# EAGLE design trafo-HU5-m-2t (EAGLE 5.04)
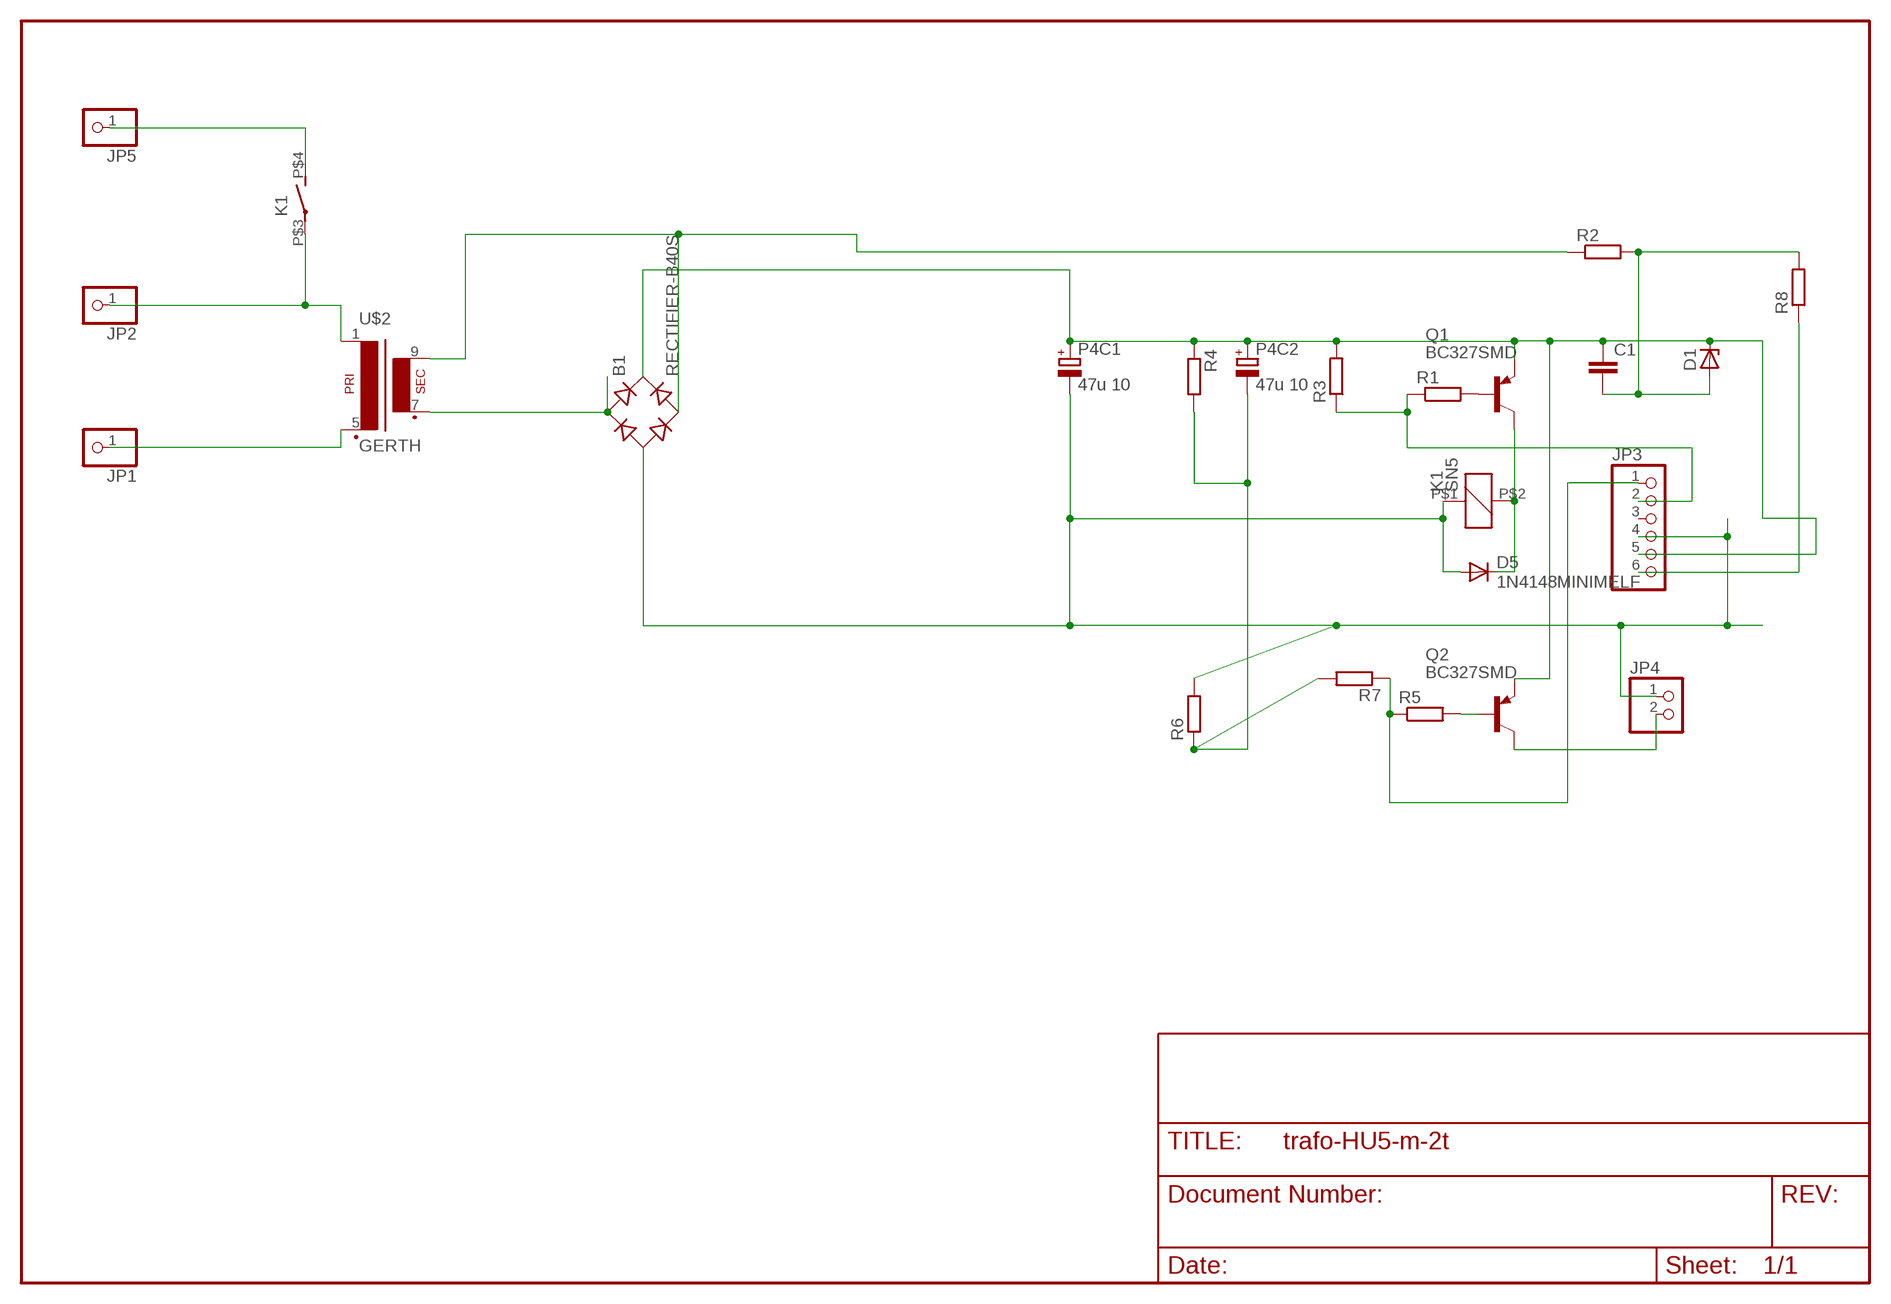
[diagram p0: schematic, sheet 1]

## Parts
B1  RECTIFIER-B40S  [B40S]
C1  C-EUC1206  [C1206]
D1  ZENER-DIODESOT23  [SOT23]
D5  1N4148MINIMELF  [MINIMELF]
JP1  PINHD-1X1  [1X01]
JP2  PINHD-1X1  [1X01]
JP3  PINHD-1X6  [1X06]
JP4  PINHD-1X2  [1X02]
JP5  PINHD-1X1  [1X01]
K1  SN5  [HU]
P4C1  47u 10  CPOL-EUE2-5  [E2-5]
P4C2  47u 10  CPOL-EUSANYO_SMD_A5  [SANYO-OSCON_SMD_A5]
Q1  BC327SMD  [SOT23-BEC]
Q2  BC327SMD  [SOT23-BEC]
R1  R-EU_R0805  [R0805]
R2  R-EU_R0805  [R0805]
R3  R-EU_R1206  [R1206]
R4  R-EU_R0805  [R0805]
R5  R-EU_R0805  [R0805]
R6  R-EU_R0805  [R0805]
R7  R-EU_R0805  [R0805]
R8  R-EU_R1206  [R1206]
U$2  GERTH  [150.06]

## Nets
N$1: JP2.1 K1.P$3(2:P) U$2.1
N$2: B1.+ C1.1 D1.3(C) JP3.5 P4C1.+ P4C2.+ Q1.E Q2.E R3.2 R4.1
N$3: B1.- D5.A JP3.4 JP4.1 K1.P$1 P4C1.- R6.2
N$4: JP5.1 K1.P$4(2:S)
N$5: JP1.1 U$2.5(P2)
N$6: B1.AC1 U$2.7(S3)
N$7: B1.AC2 R2.1 U$2.9(S4)
N$8: Q1.B R1.2
N$9: C1.2 D1.1(A) R2.2 R8.2
N$10: JP3.2 R1.1 R3.1
N$11: D5.C K1.P$2 Q1.C
N$12: JP4.2 Q2.C
N$13: JP3.1 R5.1 R7.1
N$14: JP3.6 R8.1
N$15: Q2.B R5.2
N$16: P4C2.- R4.2 R6.1 R7.2
Unconnected: JP3.3

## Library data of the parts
B1 = rectifier:RECTIFIER-: Rectifier
C1 = rcl-2:C-EU: CAPACITOR, European symbol
D1 = diode-1:ZENER-DIODE: Z-Diode
D5 = diode-1:1N4148: DIODE
JP1 JP2 JP5 = pinhead(2):PINHD-1X1: PIN HEADER
JP3 = pinhead:PINHD-1X6: PIN HEADER
JP4 = pinhead:PINHD-1X2: PIN HEADER
K1 = relay:SN*: Slim PCB Relay 1 pole 6 A SCHRACK Source: http://www.schrack.com/.. 5815.pdf
P4C1 P4C2 = rcl:CPOL-EU: POLARIZED CAPACITOR, European symbol
Q1 Q2 = transistor-pnp:BC327*: PNP Transistror
R1-R8 = rcl-2:R-EU_: RESISTOR, European symbol
U$2 = trafo:GERTH

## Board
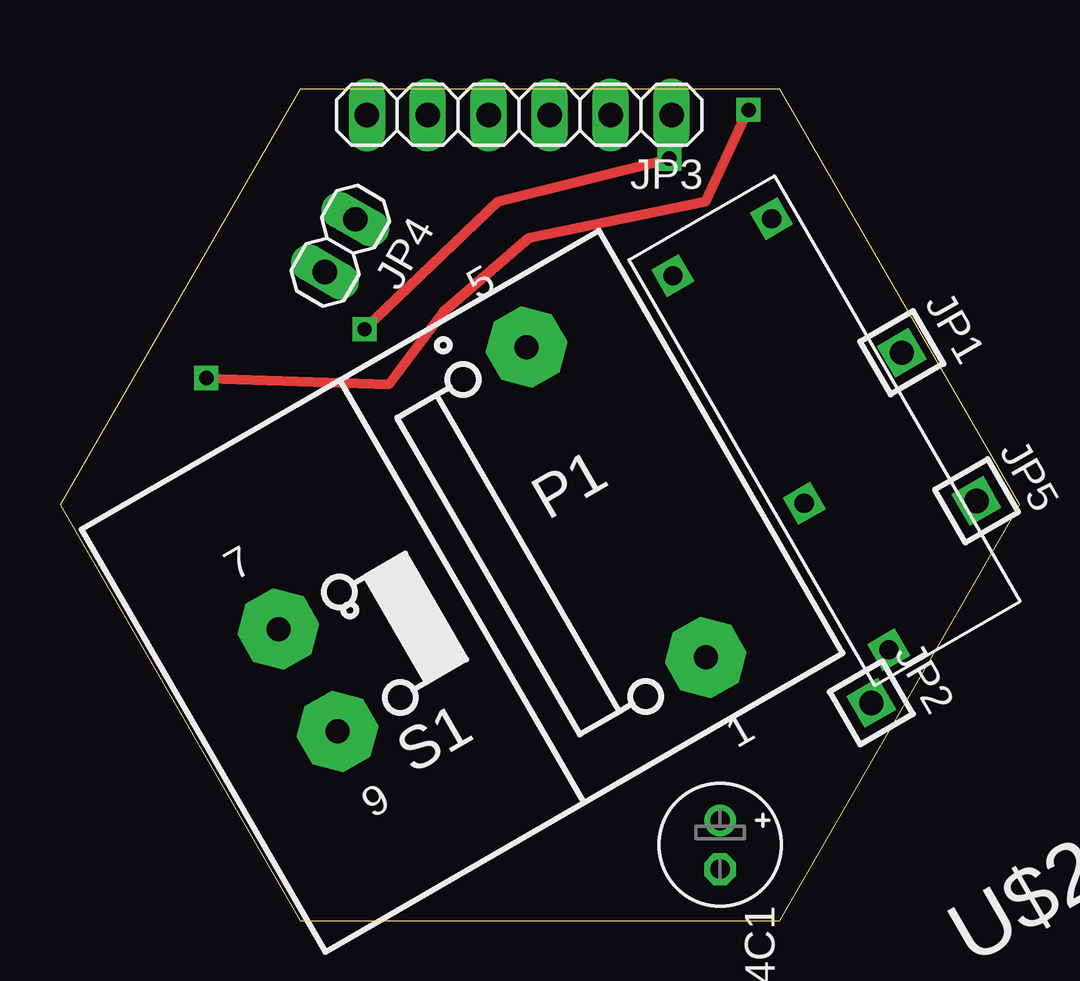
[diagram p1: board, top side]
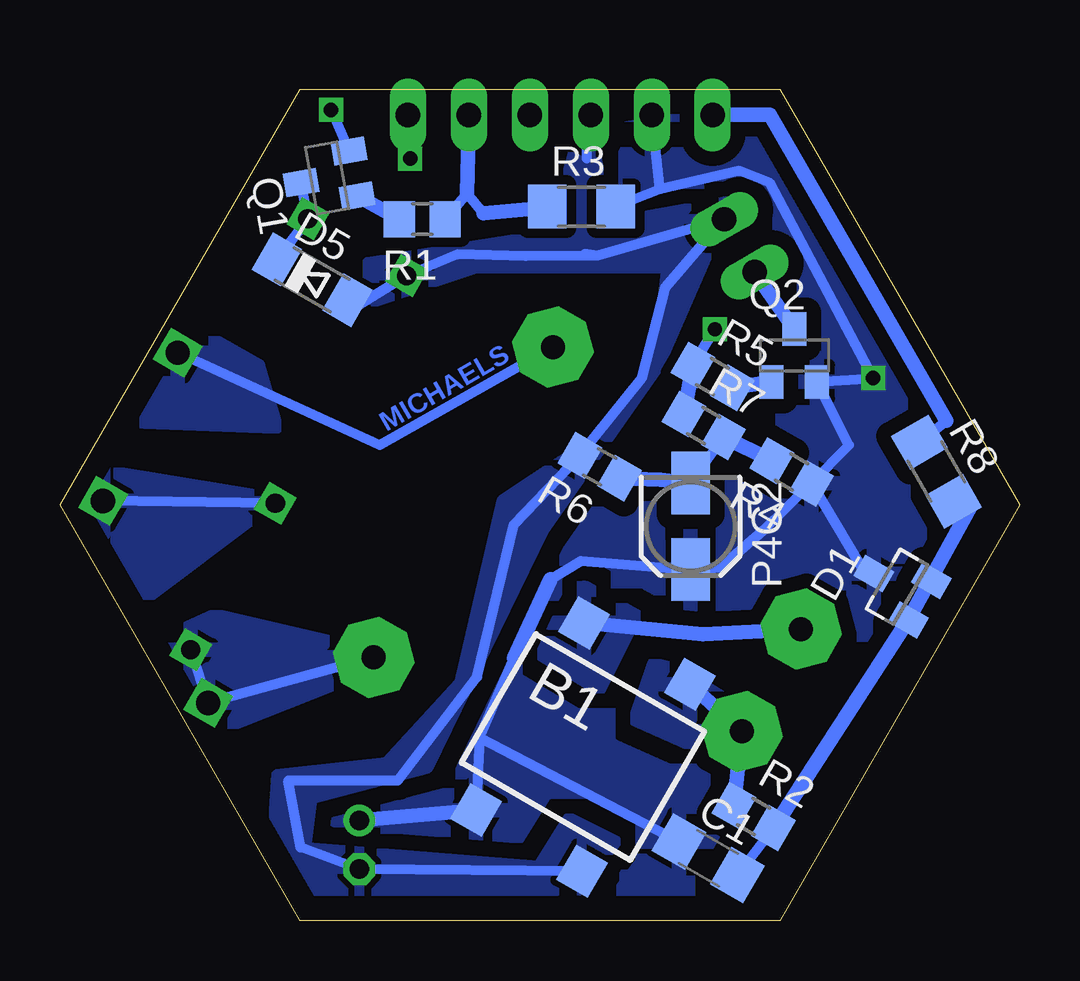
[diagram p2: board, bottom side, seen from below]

Size 40 x 34.64 mm. Coordinates in mm from the lower left corner, seen from the top.
Outline: 10,0 30,0 40,17.32 30,34.64 10,34.64 0,17.32 10,0
Copper layers (1*16): Top 0.035mm / dielectric 1.5mm / Bottom 0.035mm
Design rules "default": minimum track width 10mil, minimum drill 24mil, track to track 8mil, track to pad 8mil, pad to pad 8mil, via to via 8mil, smd to smd 8mil, copper to edge 40mil, drill to drill 8mil, minimum pad ring 10mil, minimum via ring 8mil, stop-mask expansion 4mil, vias tented up to drill 0mil, thermal gap 10mil

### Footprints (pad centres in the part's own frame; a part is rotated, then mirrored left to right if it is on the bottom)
B40S = smd 1.5 x 1.7: + -2.55,-4.5; - 2.55,-4.5; AC1 -2.55,4.5; AC2 2.55,4.5
C1206 = smd 1.6 x 1.8: 1 -1.4,0; 2 1.4,0
SOT23 = smd 1 x 1.4: 1 -0.95,-1.1; 2 0.95,-1.1; 3 0,1.1
MINIMELF = smd 1.4 x 1.8: A 1.7,0; C -1.7,0
1X01 = drill 1.016 square: 1 0,0
1X06 = drill 1.016 long: 1 -6.35,0; 2 -3.81,0; 3 -1.27,0; 4 1.27,0; 5 3.81,0; 6 6.35,0
1X02 = drill 1.016 long: 1 -1.27,0; 2 1.27,0
HU = drill 0.8 square: P$1 2.25,-9; P$2 -2.5,-9; P$3 2.25,9; P$4 2.25,1.95
E2-5 = drill 0.813 pad 1.27 round: + -1.016,0 | drill 0.813 pad 1.27 octagon: - 1.016,0
SANYO-OSCON_SMD_A5 = smd 2.6 x 1.6: + 1.8,0; - -1.8,0
SOT23-BEC = smd 1 x 1.4: B -0.95,-1.1; C 0,1.1; E 0.95,-1.1
R0805 = smd 1.3 x 1.5: 1 -0.95,0; 2 0.95,0
R1206 = smd 1.6 x 1.803: 1 -1.422,0; 2 1.422,0
150.06 = drill 1 pad 3.175 octagon: 1 -7.417,7.468; 5 -7.417,-7.468; 7 7.417,-2.464; 9 7.417,2.464

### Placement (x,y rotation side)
B1  18.2,7.23 330 bottom
C1  12.98,2.6 330 bottom
D1  5.11,13.9 60 bottom
D5  29.49,26.7 330 bottom
JP1  35.09,23.66 300 top
JP2  33.82,9.07 300 top
JP3  19.14,33.57 180 top
JP4  11.68,28.12 240 top
JP5  38.21,17.49 300 top
K1  32,20.2 210 top
P4C1  27.52,3.16 270 top
P4C2  13.71,16.43 270 bottom
Q1  28.86,30.94 100 bottom
Q2  9.39,23.55 0 bottom
R1  24.9,29.23 180 bottom
R2  11.08,4.33 330 bottom
R3  18.26,29.75 0 bottom
R4  9.5,18.69 150 bottom
R5  12.8,22.67 330 bottom
R6  17.51,18.91 150 bottom
R7  13.16,20.63 330 bottom
R8  3.46,18.7 300 bottom
U$2  16.76,13.72 210 top

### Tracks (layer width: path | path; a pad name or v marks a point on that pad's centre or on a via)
N$1
  Bottom 0.406: K1.P$3 JP2.1 U$2.1
  pour Bottom (isolate 0.406): 33.53,12.7 36.32,11.43 34.29,7.62 25.91,10.92
N$2  (via drill 0.6)
  Top 0.406: v28.7,33.78 26.92,29.97 19.56,28.45 16,25.4 13.72,22.35 v6.1,22.61
  Bottom 0.406: 22.5,7.62 21.08,10.92 | 22.5,7.62 B1.+ | 19.56,14.22 18.29,14.99 P4C2.+ 12.45,14.73 10.67,16.26 R4.1 | R4.1 6.6,14.73 D1.3 | R4.1 7.11,19.81 Q2.E v6.1,22.61 10.41,30.73 11.68,31.24 14.99,30.48 | C1.1 22.5,7.62 | v28.7,33.78 Q1.E | 14.99,30.48 JP3.5 | 14.99,30.48 R3.2
  Bottom 0.61: 21.08,10.92 19.56,14.22 | B1.+ P4C1.+
  pour Bottom (isolate 0.61, rank 6): 30.48,30.48 13.72,26.92 23.62,8.38 32,4.57 29.46,0.76 10.67,1.02 1.02,17.78 10.67,34.04
N$3
  Bottom 0.406: B1.- P4C1.- 29.97,3.05 30.48,5.84 25.91,5.84 22.61,10.16 21.08,16.51 R6.2 15.75,22.61 14.77,26.4 JP4.1 17.59,27.71 | 17.59,27.71 18.13,27.78 | 18.03,31.75 18.03,33.57 JP3.4 | 17.59,27.71 20.57,27.69 23.44,27.76 K1.P$1 27.94,25.4 D5.A
  pour Bottom (isolate 0.406): 12.19,29.97 16.51,29.21 17.27,29.97 18.03,34.04 19.05,30.48 19.05,28.7 27.18,27.43 27.18,25.65 22.61,27.18 14.73,27.18 15.24,22.86 17.78,20.07 21.59,17.53 23.37,9.91 26.42,6.6 30.99,6.1 31.24,2.54 29.72,1.02 18.29,1.27 16.76,3.3 18.8,4.32 20.07,2.29 29.72,3.05 29.46,5.08 24.64,6.35 19.81,16.26 14.99,23.11 12.45,28.96
N$4
  Bottom 0.406: K1.P$4 JP5.1
  pour Bottom (isolate 0.406): 38.61,18.8 39.62,17.02 37.08,12.95 30.99,17.53
N$5
  Bottom 0.406: U$2.5 26.67,19.81 JP1.1
  pour Bottom (isolate 0.406): 35.31,25.15 31.75,23.11 30.99,20.57 37.59,20.83 36.58,23.62
N$6
  Bottom 0.61: U$2.7 13.21,11.94 B1.AC1
  pour Bottom (isolate 0.406): 18.29,13.97 20.07,11.18 17.53,9.65 16,12.7
N$7
  Bottom 0.61: B1.AC2 U$2.9 R2.1
  pour Bottom (isolate 0.406): 14.22,10.41 15.24,10.67 16,8.38 13.72,7.37 12.19,9.14
N$8
  Bottom 0.61: R1.2 Q1.B
N$9
  Bottom 0.406: C1.2 R2.2 | 2.03,17.27 R8.2
  Bottom 0.61: R2.2 D1.1 2.03,17.27
N$10
  Bottom 0.406: R3.1 19.56,29.72 | 22.35,29.46 23.04,30.31 R1.1
  Bottom 0.61: 19.56,29.72 22.35,29.46 | 23.04,30.31 JP3.2
N$11
  Bottom 0.406: D5.C K1.P$2 Q1.C
N$12
  Bottom 0.61: Q2.C JP4.2
N$13  (via drill 0.6)
  Top 0.406: v12.7,24.64 18.29,29.97 v25.4,31.75
  Bottom 0.406: R5.1 v12.7,24.64 | v25.4,31.75 JP3.1
  Bottom 0.61: R7.1 R5.1
N$14
  Bottom 0.406: R8.1 3.05,20.83
  Bottom 0.61: JP3.6 10.41,33.57 3.05,20.83
N$15
  Bottom 0.61: Q2.B R5.2
N$16
  Bottom 0.406: R7.2 P4C2.-
  Bottom 0.61: R6.1 14.98,18.37 P4C2.- | R4.2 R7.2

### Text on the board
Bottom: MICHAELS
